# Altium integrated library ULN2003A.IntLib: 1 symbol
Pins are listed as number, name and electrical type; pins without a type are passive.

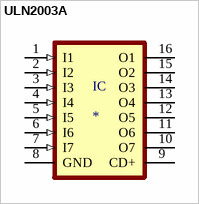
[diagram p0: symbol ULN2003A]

## ULN2003A
designator IC
Bipolar _BJT_ Transistor Array 7 NPN Darlington 50V 500mA Through Hole 16-DIP; MP: ULN2003A; MF: STMicroelectronics
footprint DIL16
pins: 1 I1 (in), 2 I2 (in), 3 I3 (in), 4 I4 (in), 5 I5 (in), 6 I6 (in), 7 I7 (in), 8 GND (power), 9 CD+, 10 O7 (oc), 11 O6 (oc), 12 O5 (oc), 13 O4 (oc), 14 O3 (oc), 15 O2 (oc), 16 O1 (oc)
